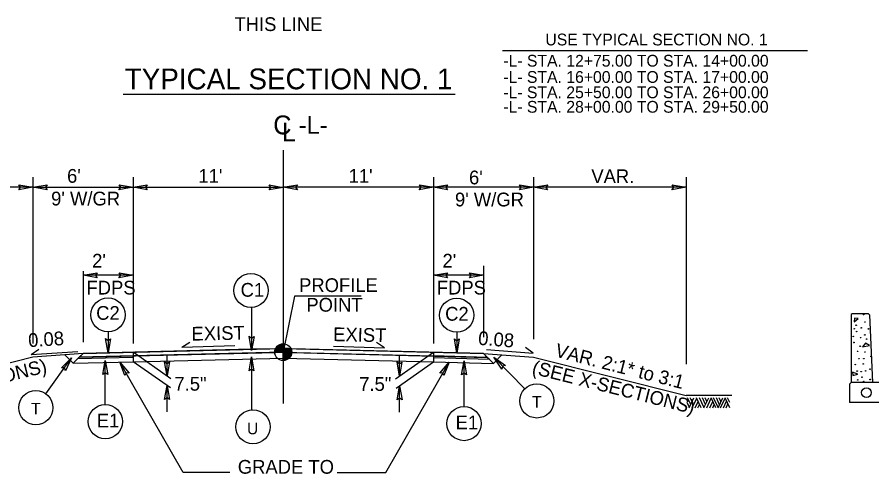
# Model space of a CAD drawing. Extents: x 573687 to 575553, y -54556 to -52223.
# Drawn here: x 574016 to 574539, y -52806 to -52526 of the extents above; entities that cross this region are included whole.
import ezdxf

# ---------------------------------------------------------------- set-up
doc = ezdxf.new("R2010")
doc.units = 0
for name, color, linetype in [('Default', 7, 'Continuous'), ('Old_Level_1', 7, 'Continuous'), ('Old_Level_35', 7, 'Continuous'), ('Prop Dimension', 7, 'Continuous'), ('Prop Dimension Text', 7, 'Continuous'), ('Typical Arrow Superelevation CELL', 7, 'Continuous'), ('Typical Bridge Rail CELL', 7, 'Continuous'), ('Typical Terminator CELL', 7, 'Continuous'), ('Typical Text Centerline CELL', 7, 'Continuous'), ('Typical Text Grade Point CELL', 7, 'Continuous'), ('Typical Text Label CELL', 7, 'Continuous')]:
    doc.layers.add(name, color=color, linetype=linetype)

msp = doc.modelspace()

# ---------------------------------------------------------------- linework, layer by layer
at = {"layer": 'Old_Level_1'}
for p, q in [((574528.15, -52710.11), (574527.99, -52712.46)), ((574527.99, -52712.46), (574530.49, -52710.39)), ((574530.49, -52710.39), (574528.15, -52710.11)), ((574534.9, -52725.58), (574533.15, -52727.7)), ((574537.31, -52726.85), (574534.9, -52725.58)), ((574054.33, -52734.03), (574179.1, -52730.98)), ((574054.33, -52734.03), (574174.42, -52731.1)), ((574056.64, -52731.73), (574179.04, -52728.73)), ((574159.54, -52729.21), (574056.64, -52731.73)), ((574087.24, -52730.98), (574087.24, -52736.83)), ((574179.04, -52730.98), (574087.24, -52733.23)), ((574173.85, -52728.86), (574159.79, -52729.2)), ((574179.04, -52728.73), (574173.85, -52728.86)), ((574174.42, -52731.1), (574179.04, -52730.98)), ((574178.98, -52730.98), (574303.75, -52734.16)), ((574179.04, -52728.73), (574301.44, -52731.85)), ((574179.65, -52728.75), (574179.04, -52728.73)), ((574179.04, -52728.85), (574179.04, -52728.73)), ((574181.22, -52731.04), (574179.04, -52728.85)), ((574179.04, -52728.85), (574181.22, -52731.04)), ((574179.04, -52729.58), (574179.04, -52728.85)), ((574179.04, -52728.85), (574179.04, -52728.85)), ((574179.04, -52729.58), (574180.47, -52731.02)), ((574180.47, -52731.02), (574179.04, -52729.58)), ((574179.04, -52729.58), (574179.04, -52730.32)), ((574179.04, -52730.98), (574179.04, -52729.58)), ((574179.04, -52729.58), (574179.04, -52729.58)), ((574179.04, -52730.32), (574179.72, -52731)), ((574179.04, -52730.32), (574179.04, -52730.98)), ((574179.72, -52731), (574179.04, -52730.32)), ((574179.04, -52730.98), (574270.84, -52733.32)), ((574179.04, -52730.98), (574179.72, -52731)), ((574180.41, -52728.77), (574179.65, -52728.75)), ((574179.65, -52728.75), (574181.96, -52731.06)), ((574181.96, -52731.06), (574179.65, -52728.75)), ((574179.72, -52731), (574180.47, -52731.02)), ((574182.72, -52731.08), (574180.41, -52728.77)), ((574181.17, -52728.79), (574180.41, -52728.77)), ((574180.41, -52728.77), (574182.72, -52731.08)), ((574180.47, -52731.02), (574181.22, -52731.04)), ((574181.9, -52728.8), (574181.17, -52728.79)), ((574181.17, -52728.79), (574183.46, -52731.1)), ((574183.46, -52731.1), (574181.17, -52728.79)), ((574181.22, -52731.04), (574181.96, -52731.06)), ((574183.82, -52730.7), (574181.9, -52728.8)), ((574182.66, -52728.82), (574181.9, -52728.8)), ((574181.9, -52728.8), (574183.82, -52730.7)), ((574181.96, -52731.06), (574182.72, -52731.08)), ((574184.01, -52730.15), (574182.66, -52728.82)), ((574184.21, -52728.86), (574182.66, -52728.82)), ((574182.66, -52728.82), (574184.01, -52730.15)), ((574182.72, -52731.08), (574183.46, -52731.1)), ((574183.46, -52731.1), (574183.64, -52731.1)), ((574183.64, -52731.1), (574303.75, -52734.16)), ((574301.44, -52731.85), (574184.21, -52728.86)), ((574270.84, -52731.07), (574270.84, -52736.92)), ((574533.15, -52727.7), (574537.31, -52726.85)), ((574026.04, -52734.02), (573933.79, -52757.08)), ((574056.64, -52731.73), (574026.04, -52734.02)), ((574045.48, -52732.56), (574050.64, -52737.73)), ((574056.64, -52731.73), (574050.64, -52737.73)), ((574053.49, -52734.88), (574087.24, -52734.06)), ((574056.64, -52731.73), (574054.33, -52734.03)), ((574087.24, -52736.83), (574179.18, -52734.58)), ((574178.89, -52734.58), (574270.84, -52736.92)), ((574270.84, -52734.33), (574304.79, -52735.19)), ((574301.44, -52731.85), (574332.04, -52734.14)), ((574301.44, -52731.85), (574307.45, -52737.85)), ((574303.75, -52734.16), (574301.44, -52731.85)), ((574312.61, -52732.69), (574307.45, -52737.85)), ((574332.04, -52734.14), (574425.3, -52757.45)), ((574050.64, -52737.73), (574087.24, -52736.83)), ((574270.84, -52736.92), (574307.45, -52737.85)), ((574527.04, -52743.29), (574527.28, -52745.29)), ((574530.31, -52744.5), (574527.04, -52743.29)), ((574527.28, -52745.29), (574530.31, -52744.5)), ((574525.23, -52750.54), (574525.23, -52761.86)), ((574918.83, -52749.61), (574526.16, -52749.61)), ((574453.22, -52757.45), (574425.3, -52757.45)), ((574427.3, -52764.77), (574425.91, -52761.81)), ((574428.07, -52763.11), (574426.12, -52758.9)), ((574427.12, -52765.16), (574430.01, -52758.9)), ((574428.9, -52761.29), (574427.83, -52758.9)), ((574428.99, -52765.16), (574431.75, -52759.19)), ((574430.77, -52765.16), (574432.66, -52761.1)), ((574434.54, -52765.16), (574431.64, -52758.9)), ((574436.25, -52764.99), (574433.44, -52758.9)), ((574437.15, -52763.04), (574435.25, -52758.9)), ((574436.19, -52765.16), (574439.07, -52758.9)), ((574437.96, -52761.22), (574436.91, -52758.9)), ((574437.89, -52765.16), (574440.66, -52759.22)), ((574439.69, -52765.16), (574441.56, -52761.1)), ((574443.47, -52765.16), (574440.53, -52758.9)), ((574444.88, -52764.95), (574442.07, -52758.9)), ((574445.71, -52763.16), (574443.76, -52758.9)), ((574444.78, -52765.16), (574447.67, -52758.89)), ((574446.6, -52761.27), (574445.5, -52758.9)), ((574446.34, -52765.16), (574449.13, -52759.09)), ((574448.05, -52765.16), (574449.98, -52760.91)), ((574451.97, -52765.16), (574449.07, -52758.9)), ((574449.69, -52765.16), (574450.82, -52762.69)), ((574451.97, -52761.81), (574450.63, -52758.9)), ((574919.76, -52761.86), (574525.23, -52761.86)), ((574432.53, -52765.16), (574433.54, -52763)), ((574441.51, -52765.16), (574442.46, -52763.05))]:
    msp.add_line(p, q, dxfattribs=at)
for points in [[(574159.79, -52729.2), (574159.67, -52729.92), (574159.54, -52729.21)], [(574179.04, -52728.73), (574179.04, -52728.85), (574179.04, -52728.85)], [(574179.04, -52728.85), (574179.04, -52729.58), (574179.04, -52729.58)], [(574179.04, -52728.85), (574179.04, -52728.85)], [(574179.04, -52729.58), (574179.04, -52729.58)]]:
    msp.add_lwpolyline(points, dxfattribs=at)
for centre, radius in [((574533.76, -52707.99), 0.174), ((574529.22, -52714.52), 0.174), ((574534.58, -52712.52), 0.174), ((574528.08, -52716.67), 0.174), ((574529.51, -52718.38), 0.174), ((574532.35, -52716.1), 0.174), ((574534.5, -52720.45), 0.174), ((574536.78, -52716.74), 0.174), ((574527.48, -52721.35), 0.174), ((574527.85, -52725.1), 0.174), ((574531.9, -52722.14), 0.174), ((574535.57, -52723.01), 0.174), ((574530.11, -52730.47), 0.174), ((574531.68, -52727.35), 0.174), ((574534.55, -52730.89), 0.174), ((574530.92, -52735), 0.174), ((574533.91, -52734.95), 0.174), ((574538.35, -52733.63), 0.174), ((574528.7, -52738.59), 0.174), ((574533.57, -52738.16), 0.174), ((574537.65, -52741.39), 0.174), ((574529.82, -52742.6), 0.174), ((574532.27, -52742.9), 0.174), ((574532.79, -52746.29), 0.174), ((574535.03, -52742.47), 0.174), ((574530.19, -52747.99), 0.174), ((574533.86, -52748.85), 0.174), ((574537.79, -52747.74), 0.174), ((574535.51, -52755.74), 2.98)]:
    msp.add_circle(centre, radius, dxfattribs=at)
for start, end in [(181.4378, 207.1878), (181.4378, 207.1878), (332.7606, 358.5101), (332.7606, 337.6057), (337.6057, 344.0607), (344.0607, 358.5101)]:
    msp.add_arc((574179.03, -52728.73), 5.18, start, end, dxfattribs=at)
at = {"layer": 'Old_Level_35'}
for p, q in [((574179.04, -52728.17), (574177.05, -52726.18)), ((574179.04, -52727.45), (574177.61, -52726)), ((574179.04, -52726.72), (574178.18, -52725.86)), ((574179.04, -52725.97), (574178.85, -52725.82)), ((574179.04, -52730.98), (574179.04, -52725.79)), ((574179.04, -52730.98), (574173.85, -52730.98)), ((574174.51, -52730.98), (574173.9, -52730.36)), ((574175.26, -52730.98), (574174.01, -52729.74)), ((574175.97, -52730.98), (574174.17, -52729.18)), ((574176.71, -52730.98), (574174.4, -52728.68)), ((574177.45, -52730.98), (574174.66, -52728.22)), ((574178.18, -52730.98), (574174.98, -52727.78)), ((574178.9, -52730.98), (574175.3, -52727.38)), ((574179.04, -52730.38), (574175.7, -52727.03)), ((574179.04, -52729.64), (574176.09, -52726.72)), ((574179.04, -52728.91), (574176.55, -52726.44)), ((574179.04, -52736.17), (574179.04, -52730.98)), ((574184.2, -52730.98), (574179.04, -52730.98)), ((574179.04, -52731.1), (574182.64, -52734.72)), ((574179.64, -52730.98), (574182.98, -52734.33)), ((574180.37, -52730.98), (574183.31, -52733.91)), ((574181.12, -52730.98), (574183.58, -52733.47)), ((574181.83, -52730.98), (574183.83, -52732.96)), ((574182.56, -52730.98), (574184.02, -52732.41)), ((574183.31, -52730.98), (574184.14, -52731.83)), ((574184.04, -52730.98), (574184.2, -52731.14)), ((574179.04, -52731.83), (574182.24, -52735.04)), ((574179.04, -52732.57), (574181.81, -52735.33)), ((574179.04, -52733.31), (574181.35, -52735.62)), ((574179.04, -52734.05), (574180.83, -52735.85)), ((574179.04, -52734.76), (574180.28, -52736.01)), ((574179.04, -52735.5), (574179.66, -52736.12))]:
    msp.add_line(p, q, dxfattribs=at)
msp.add_circle((574179.03, -52730.98), 5.18, dxfattribs=at)
at = {"layer": 'Prop Dimension'}
for p, q in [((574179.04, -52607.35), (574179.04, -52762.36)), ((574026.04, -52623.97), (574026.04, -52725.77)), ((574087.24, -52623.97), (574087.24, -52725.77)), ((574270.84, -52623.97), (574270.84, -52725.77)), ((574332.04, -52623.97), (574332.04, -52723.13)), ((574425.3, -52623.97), (574425.3, -52738.27)), ((574026.04, -52630.11), (573933.79, -52630.11)), ((574026.04, -52630.11), (574087.24, -52630.11)), ((574087.24, -52630.11), (574179.04, -52630.11)), ((574270.84, -52630.11), (574179.04, -52630.11)), ((574332.04, -52630.11), (574270.84, -52630.11)), ((574425.3, -52630.11), (574332.04, -52630.11)), ((574301.44, -52678.23), (574301.44, -52721.74)), ((574056.64, -52681.46), (574056.64, -52724.97)), ((574087.24, -52683.95), (574056.64, -52683.95)), ((574301.44, -52683.95), (574270.84, -52683.95)), ((574159.67, -52703.67), (574159.67, -52729.92)), ((574072, -52718.64), (574072, -52731.35)), ((574285.16, -52718.81), (574285.16, -52731.52)), ((574033.89, -52756.48), (574049.68, -52734.55)), ((574070.22, -52763.05), (574070.22, -52736.02)), ((574107.98, -52745.55), (574107.98, -52733.33)), ((574159.6, -52733.82), (574159.6, -52766.27)), ((574250.1, -52745.65), (574250.1, -52733.42)), ((574289.55, -52764.24), (574289.55, -52736.21)), ((574326.68, -52753.39), (574307.71, -52734.15)), ((574117.93, -52804.56), (574079.2, -52737.03)), ((574241.79, -52804.56), (574280.43, -52737.17)), ((574107.98, -52767.57), (574107.98, -52751.41)), ((574250.1, -52767.66), (574250.1, -52751.5)), ((574146.36, -52804.56), (574117.93, -52804.56)), ((574211.92, -52804.56), (574241.79, -52804.56))]:
    msp.add_line(p, q, dxfattribs=at)
for points in [[(574110.4, -52747.25), (574087.24, -52730.98)], [(574247.68, -52747.34), (574270.84, -52731.07)], [(574110.06, -52752.86), (574087.24, -52736.83)], [(574248.02, -52752.96), (574270.84, -52736.92)]]:
    msp.add_lwpolyline(points, dxfattribs=at)
for centre in [(574159.28, -52693.22), (574071.93, -52708.19), (574285.08, -52708.36), (574334.02, -52760.83), (574070.22, -52773.5), (574160.53, -52776.68), (574289.55, -52774.7)]:
    msp.add_circle(centre, 10.46, dxfattribs=at)
at = {"layer": 'Prop Dimension Text'}
for p, q in [((574313, -52546.35), (574499.48, -52546.35)), ((574081.21, -52573.18), (574284.15, -52573.18)), ((574054.33, -52734.03), (574053.49, -52734.88)), ((574053.49, -52734.88), (574087.24, -52734.06)), ((574087.24, -52733.23), (574054.33, -52734.03)), ((574087.24, -52734.06), (574087.24, -52733.23)), ((574303.75, -52734.16), (574270.84, -52733.32)), ((574270.84, -52733.32), (574270.84, -52734.33)), ((574270.84, -52734.33), (574304.79, -52735.19)), ((574304.79, -52735.19), (574303.75, -52734.16))]:
    msp.add_line(p, q, dxfattribs=at)
msp.add_circle((574027.79, -52764.97), 10.46, dxfattribs=at)
at = {"layer": 'Typical Arrow Superelevation CELL'}
for p, q in [((574117.07, -52727.85), (574121.99, -52724.81)), ((574240.84, -52728.28), (574236.05, -52725.04)), ((574024.9, -52732.41), (574029.71, -52729.2)), ((574024.9, -52732.41), (574053.44, -52730.53)), ((574117.07, -52727.85), (574149.42, -52726.9)), ((574209.64, -52727.39), (574240.84, -52728.28)), ((574303.17, -52729.34), (574331.69, -52731.52)), ((574331.69, -52731.52), (574327.05, -52728.06))]:
    msp.add_line(p, q, dxfattribs=at)
at = {"layer": 'Typical Bridge Rail CELL'}
for p, q in [((574526.68, -52707.51), (574526.16, -52708.03)), ((574526.16, -52708.03), (574526.16, -52749.61)), ((574536.74, -52707.51), (574526.68, -52707.51)), ((574537.32, -52708.09), (574536.74, -52707.51)), ((574537.32, -52708.09), (574539.27, -52749.61)), ((574526.16, -52749.61), (574525.23, -52750.54))]:
    msp.add_line(p, q, dxfattribs=at)
at = {"layer": 'Typical Terminator CELL'}
for points in [[(574017.43, -52628.63), (574026.04, -52630.11), (574017.39, -52631.64), (574018.49, -52630.11)], [(574034.65, -52631.59), (574026.04, -52630.11), (574034.69, -52628.58), (574033.6, -52630.11)], [(574078.63, -52628.63), (574087.24, -52630.11), (574078.59, -52631.64), (574079.69, -52630.11)], [(574095.85, -52631.59), (574087.24, -52630.11), (574095.89, -52628.58), (574094.79, -52630.11)], [(574170.43, -52628.65), (574179.04, -52630.13), (574170.38, -52631.66), (574171.48, -52630.13)], [(574187.65, -52631.59), (574179.04, -52630.11), (574187.69, -52628.58), (574186.59, -52630.11)], [(574262.23, -52628.63), (574270.84, -52630.11), (574262.19, -52631.64), (574263.29, -52630.11)], [(574279.45, -52631.59), (574270.84, -52630.11), (574279.5, -52628.58), (574278.4, -52630.11)], [(574323.43, -52628.63), (574332.04, -52630.11), (574323.39, -52631.64), (574324.49, -52630.11)], [(574340.65, -52631.59), (574332.04, -52630.11), (574340.7, -52628.58), (574339.6, -52630.11)], [(574416.69, -52628.63), (574425.3, -52630.11), (574416.64, -52631.64), (574417.74, -52630.11)], [(574065.25, -52685.43), (574056.64, -52683.95), (574065.29, -52682.42), (574064.19, -52683.95)], [(574078.63, -52682.46), (574087.24, -52683.95), (574078.59, -52685.48), (574079.69, -52683.95)], [(574279.45, -52685.43), (574270.84, -52683.95), (574279.49, -52682.42), (574278.39, -52683.95)], [(574292.83, -52682.46), (574301.44, -52683.95), (574292.79, -52685.48), (574293.89, -52683.95)], [(574073.49, -52722.74), (574072, -52731.35), (574070.47, -52722.7), (574072, -52723.8)], [(574161.15, -52721.32), (574159.67, -52729.92), (574158.14, -52721.27), (574159.67, -52722.37)], [(574286.64, -52722.92), (574285.16, -52731.52), (574283.63, -52722.87), (574285.16, -52723.97)], [(574043.45, -52740.67), (574049.68, -52734.55), (574045.86, -52742.46), (574045.27, -52740.68)], [(574068.74, -52744.63), (574070.22, -52736.02), (574071.75, -52744.68), (574070.22, -52743.58)], [(574158.12, -52742.42), (574159.6, -52733.82), (574161.13, -52742.47), (574159.6, -52741.37)], [(574288.07, -52744.81), (574289.55, -52736.21), (574291.08, -52744.86), (574289.55, -52743.76)], [(574312.69, -52741.32), (574307.71, -52734.15), (574314.87, -52739.23), (574313.01, -52739.53)], [(574082.13, -52745.26), (574079.2, -52737.03), (574084.78, -52743.82), (574082.91, -52743.61)], [(574109.47, -52736.95), (574107.98, -52745.55), (574106.45, -52736.9), (574107.98, -52738)], [(574251.58, -52737.04), (574250.1, -52745.65), (574248.57, -52736.99), (574250.1, -52738.09)], [(574274.71, -52743.77), (574280.43, -52737.17), (574277.26, -52745.36), (574276.52, -52743.63)], [(574106.5, -52760.01), (574107.98, -52751.41), (574109.51, -52760.06), (574107.98, -52758.96)], [(574248.61, -52760.14), (574250.1, -52751.54), (574251.63, -52760.19), (574250.1, -52759.09)]]:
    msp.add_lwpolyline(points, close=True, dxfattribs=at)
at = {"layer": 'Typical Text Grade Point CELL'}
msp.add_lwpolyline([(574226.7, -52696.66), (574185.99, -52696.66), (574179.04, -52730.98)], dxfattribs=at)

# ---------------------------------------------------------------- texts
at = {"layer": 'Default'}
for s, p in [('-L- STA. 12+75.00 TO STA. 14+00.00', (574313.53, -52556.26)), ('-L- STA. 16+00.00 TO STA. 17+00.00', (574313.53, -52566.19)), ('-L- STA. 25+50.00 TO STA. 26+00.00', (574313.53, -52575.59)), ('-L- STA. 28+00.00 TO STA. 29+50.00', (574313.53, -52584.45))]:
    msp.add_text(s, height=7.2, dxfattribs=at).set_placement(p)
at = {"layer": 'Prop Dimension'}
msp.add_text("11'", height=8.415, rotation=359.9999, dxfattribs=at).set_placement((574218.97, -52627.33))
at = {"layer": 'Prop Dimension Text'}
for s, rotation, p in [(" 6'", 0.0001, (574043.75, -52627.33)), ("11'", 0.0001, (574127.17, -52627.33)), (" 6'", 359.9999, (574289.45, -52628.3)), ('VAR.', 359.9999, (574367.35, -52627.57)), ("9' W/GR", 0.0001, (574037.14, -52641.21)), ("9' W/GR", 359.9999, (574283.99, -52641.79)), (" 2'", 359.9999, (574059.08, -52679.24)), (" 2'", 359.9999, (574273.24, -52679.24)), ('FDPS', 359.9999, (574058.74, -52695.71)), ('C1', 0.0001, (574152.96, -52697.07)), ('FDPS', 359.9999, (574272.91, -52695.71)), ('C2', 0.0001, (574064.68, -52711.19)), ('C2', 0.0001, (574277.98, -52711.73)), ('7.5"', 0.0001, (574112.5, -52754.57)), ('7.5"', 0.0001, (574225.46, -52754.69)), ('E1', 0.0001, (574065.06, -52777.04)), ('E1', 0.0001, (574284.39, -52778.23))]:
    msp.add_text(s, height=8.415, rotation=rotation, dxfattribs=at).set_placement(p)
for s, p in [('T', (574024.89, -52769.12)), ('T', (574331.12, -52764.99)), ('U', (574156.87, -52781.26))]:
    msp.add_text(s, height=7.11, dxfattribs=at).set_placement(p)
at = {"layer": 'Typical Text Centerline CELL'}
for s, height, p in [('C', 11.53, (574172.9, -52597.69)), ('L', 11.53, (574178.13, -52602.02)), ('-L-', 10.808, (574188.5, -52597.38))]:
    msp.add_text(s, height=height, rotation=0.0001, dxfattribs=at).set_placement(p)
at = {"layer": 'Typical Text Grade Point CELL'}
for s, p in [('PROFILE ', (574188.7, -52694.19)), ('POINT', (574193.14, -52706.21))]:
    msp.add_text(s, height=8.415, rotation=0.0001, dxfattribs=at).set_placement(p)
at = {"layer": 'Typical Text Label CELL'}
for s, height, rotation, p in [('THIS LINE', 8.415, 0.0001, (574149.2, -52534.48)), ('USE TYPICAL SECTION NO. 1', 7.2, 360, (574339.26, -52543.27)), ('TYPICAL SECTION NO. 1', 12.7159, 0.0001, (574082.14, -52570.13)), ('EXIST', 8.415, 1.1917, (574123.03, -52723.96)), ('EXIST', 8.415, 358.8083, (574209.46, -52724.22)), (' 0.08', 8.415, 3.4327, (574020.23, -52728.12)), (' 0.08', 8.415, 355.6177, (574294.82, -52726.23)), ('VAR. 2:1* to 3:1', 8.415, 345.6447, (574344.65, -52733.62)), ('(SEE X-SECTIONS)', 8.415, 13.8399, (573936.2, -52767.56)), ('(SEE X-SECTIONS)', 8.415, 345.8737, (574330.58, -52744.06)), ('GRADE TO ', 8.415, 0.0001, (574151.25, -52805.39))]:
    msp.add_text(s, height=height, rotation=rotation, dxfattribs=at).set_placement(p)

doc.saveas('drawing.dxf')
